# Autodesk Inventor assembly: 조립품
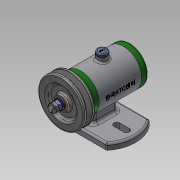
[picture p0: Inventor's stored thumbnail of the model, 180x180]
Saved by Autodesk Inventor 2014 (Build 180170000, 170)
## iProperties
Created: 2017-12
Part Number: 조립품
Document SubType Name: Assembly
Designer: 학생용
Author: 학생용
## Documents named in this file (14)
- C:\Users\학생용\Desktop\471207V1014\조립품.iam
- C:\Users\학생용\Desktop\471207V1014\V벨트풀리.ipt
- C:\Users\학생용\Desktop\471207V1014\고무캡.ipt
- C:\Users\학생용\Desktop\471207V1014\너트 M 8.ipt
- C:\Users\학생용\Desktop\471207V1014\뒤커버.ipt
- C:\Users\학생용\Desktop\471207V1014\베어링 15 x 32 x 9.ipt
- C:\Users\학생용\Desktop\471207V1014\본체.ipt
- C:\Users\학생용\Desktop\471207V1014\볼트 M4 x 12.ipt
- C:\Users\학생용\Desktop\471207V1014\스프링와셔 8.ipt
- C:\Users\학생용\Desktop\471207V1014\앞커버.ipt
- C:\Users\학생용\Desktop\471207V1014\오일 실 15 25 7.ipt
- C:\Users\학생용\Desktop\471207V1014\와셔 8x17.ipt
- C:\Users\학생용\Desktop\471207V1014\축.ipt
- C:\Users\학생용\Desktop\471207V1014\키 3 x 3 x 12.ipt
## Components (2 placed, 2 different names)
1. V벨트풀리:1
2. 고무캡:1
